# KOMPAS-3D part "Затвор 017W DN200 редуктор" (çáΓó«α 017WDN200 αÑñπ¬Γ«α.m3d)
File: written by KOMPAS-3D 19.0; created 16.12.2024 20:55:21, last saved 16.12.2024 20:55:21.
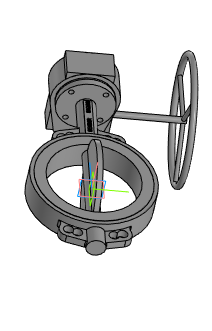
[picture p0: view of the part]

Document properties: Автор: Евгений; Полное имя файла: ..\Затвор 017WDN200 редуктор.a3d

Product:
- Part/product: Затвор 017W DN200 редуктор
    Масса: 31.6907

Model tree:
1. Операция без истории:1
